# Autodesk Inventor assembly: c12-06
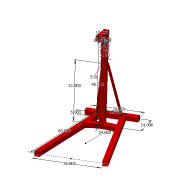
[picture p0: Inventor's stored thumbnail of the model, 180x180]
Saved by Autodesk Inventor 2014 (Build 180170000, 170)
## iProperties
Created: 2011-01
Part Number: c12-06
Document SubType Name: Assembly
Designer: Thom Tremblay
_SolveAssemblyDoc: Frame Generator Solve Assembly
_Version: 15.0.0
Author: Thom Tremblay
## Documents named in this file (3)
- C:\Inventor 2014 Essentials\Assemblies\Chapter 12\c12-06.iam
- C:\Inventor 2014 Essentials\Assemblies\Chapter 12\Frame\Frame c12-06.iam
- C:\Inventor 2014 Essentials\Parts\Chapter 12\c12-02.ipt
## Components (2 placed, 2 different names)
1. c12-02:1
2. Frame c12-06:1 [sub-assembly]
